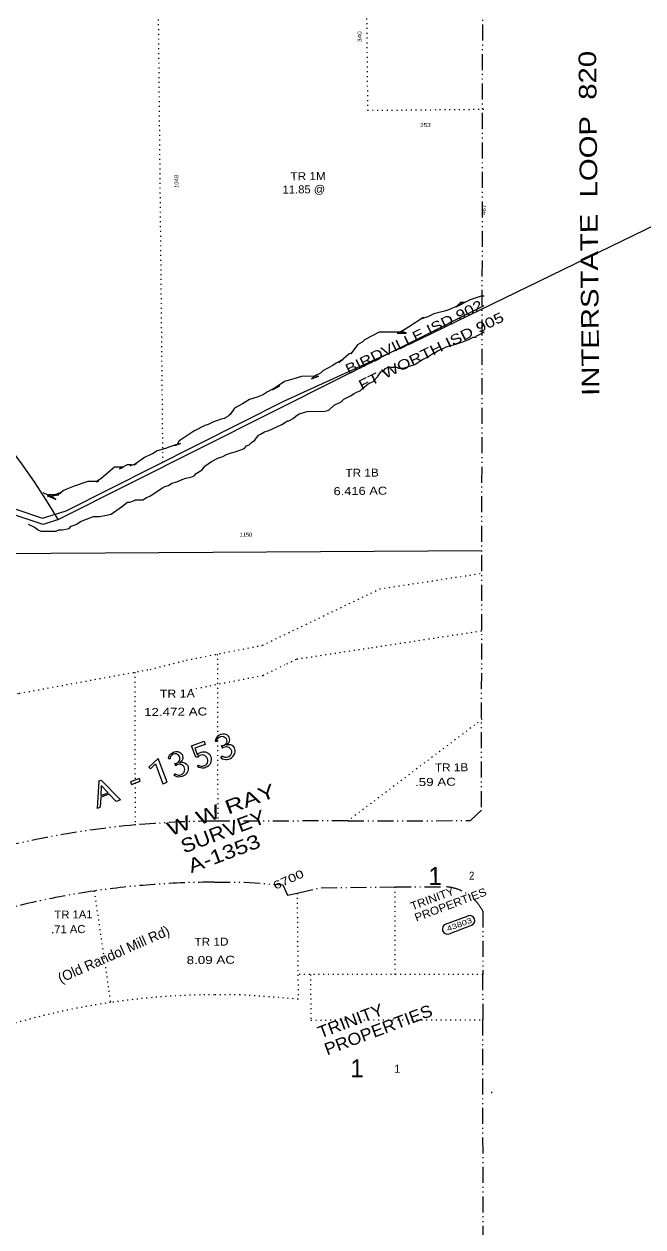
# Model space of a CAD drawing. Extents: x 2356373 to 2371954, y 6966197 to 6989612.
# Drawn here: x 2363330 to 2364566, y 6968599 to 6971002 of the extents above; entities that cross this region are included whole.
import ezdxf

# ---------------------------------------------------------------- set-up
doc = ezdxf.new("R2010")
doc.units = 0
doc.header["$LTSCALE"] = 6.4
doc.linetypes.add('DASH_DOUBLE_DOT', pattern=[9.2, 5, -1.2, 0.3, -1.2, 0.3, -1.2])
doc.linetypes.add('DOTTED', pattern=[1.5, 0.3, -1.2])
for name, color, linetype in [('10', 7, 'Continuous'), ('11', 7, 'Continuous'), ('18', 7, 'Continuous'), ('20', 7, 'Continuous'), ('21', 7, 'Continuous'), ('22', 7, 'Continuous'), ('24', 7, 'Continuous'), ('25', 7, 'Continuous')]:
    doc.layers.add(name, color=color, linetype=linetype)
for name, color, linetype, lineweight in [('12', 7, 'Continuous', 13), ('15', 7, 'Continuous', 13), ('16', 7, 'DOTTED', 13), ('17', 7, 'Continuous', 13), ('19', 7, 'Continuous', 13), ('23', 7, 'Continuous', 13), ('4', 7, 'Continuous', 13), ('5', 7, 'DOTTED', 13), ('8', 7, 'Continuous', 13)]:
    doc.layers.add(name, color=color, linetype=linetype, lineweight=lineweight)

msp = doc.modelspace()

# ---------------------------------------------------------------- linework, layer by layer
at = {"layer": '15', "linetype": 'DASH_DOUBLE_DOT'}
for p, q in [((2364243.948, 6969438.017), (2364247.165, 6971493.721)), ((2364243.66, 6969432.062), (2364222.253, 6969410.944)), ((2363977.113, 6969410.409), (2363710.454, 6969409.753)), ((2363977.113, 6969410.409), (2364222.253, 6969410.944)), ((2364071.25, 6969278.679), (2364166.419, 6969278.924)), ((2364246.32, 6969229.78), (2364246.5, 6969103.93)), ((2364247.455, 6969013.165), (2364246.5, 6969103.93)), ((2364251.572, 6966626.517), (2364246.452, 6969018.362))]:
    msp.add_line(p, q, dxfattribs=at)
at = {"layer": '15'}
msp.add_line((2364264.196, 6968869.35), (2364264.225, 6968866.351), dxfattribs=at)
msp.add_line((2364264.196, 6968869.35), (2364264.225, 6968866.351), dxfattribs=at)
at = {"layer": '15', "linetype": 'DASH_DOUBLE_DOT'}
for points in [[(2363710.112, 6969288.003), (2363769.752, 6969288.106), (2363847.171, 6969282.389), (2363856.423, 6969261.967), (2363875.643, 6969266.149)], [(2363875.643, 6969266.149), (2363923.391, 6969276.974), (2364071.249, 6969278.688)]]:
    msp.add_lwpolyline(points, dxfattribs=at)
for centre, radius, start, end in [((2363714.863, 6967616.669), 1793.09, 90.14089, 95.20879), ((2363714.863, 6967616.669), 1793.09, 95.20879, 105.95539), ((2363712.995, 6967614.916), 1673.09, 90.09871, 98.33989), ((2363712.995, 6967614.916), 1673.09, 98.33989, 106.91324), ((2364166.651, 6969188.925), 90, 27.33233, 90.1476)]:
    msp.add_arc(centre, radius, start, end, dxfattribs=at)
at = {"layer": '16'}
msp.add_lwpolyline([(2364248.654, 6970831.173), (2364017.008, 6970828.899), (2364013.67, 6971168.774)], dxfattribs=at)
at = {"layer": '17'}
for p, q in [((2363712.229, 6969569.95), (2363715.735, 6969569.184)), ((2364172.174, 6969203.816), (2364217.495, 6969220.657)), ((2364179.355, 6969185.092), (2364224.178, 6969201.928))]:
    msp.add_line(p, q, dxfattribs=at)
for points in [[(2363726.024, 6969539.643), (2363723.558, 6969536.219), (2363726.571, 6969534.649), (2363729.581, 6969533.629), (2363733.085, 6969533.114), (2363736.083, 6969533.243), (2363739.575, 6969533.978), (2363742.562, 6969535.258), (2363745.044, 6969537.031), (2363747.521, 6969539.305), (2363749.494, 6969541.922), (2363750.966, 6969544.886), (2363751.936, 6969547.796), (2363751.906, 6969550.844), (2363751.378, 6969553.838), (2363750.35, 6969556.578), (2363748.326, 6969559.007), (2363745.81, 6969560.833), (2363743.298, 6969562.106), (2363740.293, 6969562.628), (2363737.296, 6969562.397), (2363734.307, 6969561.468), (2363736.292, 6969562.887), (2363738.273, 6969564.706), (2363739.752, 6969566.97), (2363740.724, 6969569.48), (2363741.199, 6969572.134), (2363740.675, 6969574.827), (2363740.148, 6969577.371), (2363738.626, 6969579.656), (2363736.609, 6969581.484), (2363734.095, 6969582.91), (2363730.588, 6969583.777), (2363727.088, 6969583.842), (2363723.595, 6969583.108), (2363720.112, 6969581.674), (2363717.134, 6969579.495), (2363714.661, 6969576.72), (2363713.194, 6969573.508), (2363712.229, 6969569.95)], [(2363715.735, 6969569.184), (2363715.71, 6969571.733), (2363716.686, 6969574.142), (2363718.165, 6969576.256), (2363720.149, 6969577.925), (2363722.637, 6969578.999), (2363725.133, 6969579.423), (2363727.634, 6969579.147), (2363730.142, 6969578.273), (2363732.158, 6969576.694), (2363733.677, 6969574.709), (2363734.7, 6969572.319), (2363735.225, 6969569.726), (2363734.752, 6969567.121), (2363733.774, 6969564.763), (2363732.295, 6969562.75), (2363729.809, 6969561.224), (2363727.319, 6969560.351), (2363724.824, 6969560.076), (2363726.365, 6969555.792), (2363724.824, 6969560.076), (2363726.365, 6969555.792), (2363728.847, 6969557.416), (2363731.337, 6969558.389), (2363734.334, 6969558.718), (2363736.837, 6969558.345), (2363739.347, 6969557.319), (2363741.361, 6969555.639), (2363743.383, 6969553.51), (2363744.407, 6969550.971), (2363744.932, 6969548.275), (2363744.46, 6969545.572), (2363743.487, 6969542.813), (2363742.01, 6969540.5), (2363739.528, 6969538.626), (2363737.042, 6969537.402), (2363734.048, 6969536.873), (2363731.047, 6969537.093), (2363728.538, 6969538.068), (2363726.024, 6969539.643)], [(2363712.229, 6969569.95), (2363715.735, 6969569.184), (2363712.229, 6969569.95)], [(2363622.105, 6969534.073), (2363618.599, 6969534.84), (2363622.105, 6969534.073)], [(2363633.234, 6969520.686), (2363631.193, 6969524.966), (2363633.234, 6969520.686)], [(2363726.024, 6969539.643), (2363723.558, 6969536.219), (2363726.024, 6969539.643)], [(2363629.927, 6969501.108), (2363632.393, 6969504.532), (2363629.927, 6969501.108)], [(2363678.709, 6969521.983), (2363676.737, 6969519.165), (2363678.709, 6969521.983)]]:
    msp.add_lwpolyline(points, dxfattribs=at)
for points in [[(2363648.381, 6969505.388), (2363649.856, 6969507.703), (2363650.83, 6969510.461), (2363651.304, 6969513.167), (2363650.777, 6969515.861), (2363649.752, 6969518.4), (2363647.732, 6969520.529), (2363645.715, 6969522.208), (2363643.206, 6969523.234), (2363640.703, 6969523.608), (2363637.707, 6969523.279), (2363635.217, 6969522.306), (2363633.234, 6969520.686), (2363631.193, 6969524.966), (2363634.19, 6969525.195), (2363636.179, 6969526.114), (2363638.664, 6969527.638), (2363640.144, 6969529.651), (2363641.121, 6969532.01), (2363641.594, 6969534.615), (2363641.071, 6969537.209), (2363640.046, 6969539.598), (2363638.527, 6969541.583), (2363636.512, 6969543.112), (2363634.005, 6969544.038), (2363631.503, 6969544.313), (2363629.008, 6969543.887), (2363626.519, 6969542.814), (2363624.535, 6969541.147), (2363623.056, 6969539.032), (2363622.079, 6969536.622), (2363622.105, 6969534.073), (2363618.599, 6969534.84), (2363619.564, 6969538.397), (2363621.032, 6969541.611), (2363623.504, 6969544.385), (2363626.482, 6969546.564), (2363629.967, 6969547.997), (2363633.459, 6969548.732), (2363636.957, 6969548.665), (2363640.467, 6969547.8), (2363642.979, 6969546.375), (2363644.997, 6969544.544), (2363646.518, 6969542.262), (2363647.044, 6969539.717), (2363647.57, 6969537.023), (2363647.096, 6969534.368), (2363646.121, 6969531.86), (2363644.643, 6969529.595), (2363642.661, 6969527.777), (2363640.677, 6969526.358), (2363643.667, 6969527.287), (2363646.662, 6969527.517), (2363649.668, 6969526.996), (2363652.179, 6969525.722), (2363654.697, 6969523.897), (2363656.72, 6969521.467), (2363657.747, 6969518.728), (2363658.275, 6969515.733), (2363658.306, 6969512.685), (2363657.336, 6969509.776), (2363655.864, 6969506.812), (2363653.891, 6969504.194), (2363651.414, 6969501.92), (2363648.931, 6969500.146), (2363645.945, 6969498.867), (2363642.454, 6969498.133), (2363639.454, 6969498.003), (2363635.95, 6969498.519), (2363632.942, 6969499.539), (2363629.927, 6969501.108), (2363632.393, 6969504.532), (2363634.908, 6969502.958), (2363637.917, 6969501.988), (2363640.417, 6969501.762), (2363643.413, 6969502.291), (2363645.898, 6969503.516), (2363648.381, 6969505.388)], [(2363692.757, 6969516.721), (2363689.767, 6969515.843), (2363686.27, 6969515.66), (2363682.765, 6969516.124), (2363679.255, 6969517.339), (2363676.737, 6969519.165), (2363678.709, 6969521.983), (2363681.222, 6969520.658), (2363683.729, 6969519.832), (2363686.23, 6969519.607), (2363688.727, 6969520.031), (2363691.216, 6969520.956), (2363693.2, 6969522.424), (2363695.182, 6969524.343), (2363696.659, 6969526.608), (2363697.132, 6969529.262), (2363697.105, 6969532.011), (2363696.58, 6969534.655), (2363695.556, 6969537.094), (2363693.536, 6969539.173), (2363691.521, 6969540.805), (2363689.012, 6969541.828), (2363686.507, 6969542.255), (2363683.511, 6969541.974), (2363681.021, 6969541.05), (2363678.537, 6969539.576), (2363677.057, 6969537.562), (2363673.554, 6969537.877), (2363664.834, 6969560.586), (2363689.735, 6969569.879), (2363692.299, 6969563.205), (2363671.383, 6969555.452), (2363676.515, 6969541.806), (2363678.491, 6969544.173), (2363680.973, 6969546.049), (2363683.957, 6969547.427), (2363686.449, 6969548.252), (2363689.446, 6969548.481), (2363692.45, 6969548.061), (2363695.458, 6969547.09), (2363697.972, 6969545.566), (2363700.492, 6969543.49), (2363702.015, 6969541.057), (2363703.542, 6969538.322), (2363704.071, 6969535.378), (2363704.1, 6969532.33), (2363703.631, 6969529.326), (2363702.664, 6969526.017), (2363701.193, 6969523.003), (2363698.719, 6969520.38), (2363696.241, 6969518.256), (2363692.757, 6969516.721)], [(2363592.706, 6969524.487), (2363607.597, 6969484.443), (2363616.065, 6969487.527), (2363598.104, 6969534.938), (2363579.776, 6969517.912), (2363582.808, 6969514.543), (2363592.706, 6969524.487)], [(2363484.061, 6969491.528), (2363522.932, 6969452.671), (2363514.466, 6969449.438), (2363500.325, 6969464.095), (2363483.393, 6969457.681), (2363482.591, 6969437.577), (2363477.113, 6969435.475), (2363480.574, 6969490.246), (2363484.061, 6969491.528)], [(2363483.362, 6969460.78), (2363498.304, 6969466.326), (2363484.161, 6969481.332), (2363483.362, 6969460.78)], [(2363545.127, 6969482.98), (2363562.061, 6969489.445), (2363560.507, 6969494.778), (2363543.076, 6969488.31), (2363545.127, 6969482.98)]]:
    msp.add_lwpolyline(points, close=True, dxfattribs=at)
for centre, start, end in [((2364220.586, 6969211.295), 290.56276, 110.56276), ((2364175.764, 6969194.459), 110.56276, 290.56276)]:
    msp.add_arc(centre, 9.997, start, end, dxfattribs=at)
at = {"layer": '23'}
for points in [[(2363414.02, 6970029.786), (2363850.745, 6970249.519), (2364123.451, 6970373.865), (2364831.881, 6970717.933), (2365090.947, 6970907.728), (2365131.196, 6970983.103), (2365499.957, 6971099.096), (2365745.133, 6971176.384), (2365908.693, 6971318.452), (2366016.367, 6971450.575)], [(2361736.506, 6969313.397), (2361856.463, 6969314.575), (2361996.962, 6969361.742), (2362090.297, 6969426.942), (2362123.339, 6969523.541), (2362263.567, 6969598.299), (2362349.636, 6969690.819), (2362368.682, 6969787.381), (2362357.915, 6969865.754), (2362295.204, 6970041.491), (2362521.874, 6970374.229), (2362630.364, 6970423.382), (2362757.7, 6970385.543), (2363200.677, 6970070.678), (2363367.181, 6970014.731), (2363414.02, 6970029.786)]]:
    msp.add_lwpolyline(points, dxfattribs=at)
at = {"layer": '4'}
msp.add_line((2360061.937, 6969925.881), (2364244.75, 6969950.412), dxfattribs=at)
at = {"layer": '5', "linetype": 'Continuous'}
msp.add_line((2363398.338, 6970012.187), (2364249.534, 6970439.768), dxfattribs=at)
at = {"layer": '5'}
for p, q in [((2364024.04, 6969756.457), (2364244.937, 6969790.146)), ((2363716.296, 6969743.535), (2363717.114, 6969409.77)), ((2363875.065, 6969733.736), (2364019.936, 6969755.831)), ((2363807.146, 6969701.04), (2363851.398, 6969722.343)), ((2363855.32, 6969724.231), (2363875.065, 6969733.736)), ((2363551.38, 6969707.454), (2363552.076, 6969402.354)), ((2363664.342, 6969673.051), (2363807.146, 6969701.04)), ((2364245.315, 6969613.433), (2363977.113, 6969410.409)), ((2363470.321, 6969270.313), (2363502.945, 6969047.696)), ((2364071.5, 6969103.679), (2364071.25, 6969278.679)), ((2364246.5, 6969103.93), (2363877.283, 6969103.401))]:
    msp.add_line(p, q, dxfattribs=at)
for points in [[(2364013.67, 6971168.774), (2363596.821, 6971164.68), (2363607.111, 6970117.06)], [(2363221.955, 6969340.683), (2363083.697, 6969567.425), (2363044.821, 6969611.819), (2363108.677, 6969634.872), (2363174.686, 6969645.694), (2363320.71, 6969665.189), (2363582.098, 6969713.083), (2363654.728, 6969731.465), (2363806.637, 6969761.245), (2364040.422, 6969873.802), (2364244.679, 6969904.963)], [(2363875.643, 6969266.149), (2363877.775, 6969054.52), (2363761.642, 6969063.096), (2363710.492, 6969063.008)], [(2363902.24, 6969103.437), (2363903.195, 6969012.672), (2364247.455, 6969013.165)]]:
    msp.add_lwpolyline(points, dxfattribs=at)
at = {"layer": '5', "linetype": 'Continuous'}
msp.add_lwpolyline([(2363399.198, 6970012.146), (2363368.305, 6970002.145), (2363223.868, 6970050.513), (2362779.888, 6970365.867), (2362626.481, 6970411.347), (2362489.134, 6970348.715), (2362254.566, 6970005.802), (2362313.172, 6969840.621)], dxfattribs=at)
msp.add_arc((2361987.831, 6969171.803), 1641.882, 30.78676, 79.82976, dxfattribs=at)
at = {"layer": '5'}
for start, end in [(98.34001, 107.38687), (90.09871, 98.34001)]:
    msp.add_arc((2363712.986, 6967614.92), 1448.09, start, end, dxfattribs=at)
at = {"layer": '8'}
for points in [[(2364249.492, 6970458.481), (2364243.588, 6970458.423), (2364221.668, 6970450.909), (2364192.82, 6970436.13), (2364202.717, 6970446.325), (2364210.714, 6970446.403), (2364190.818, 6970436.41), (2364183.844, 6970434.042), (2364179.868, 6970431.705), (2364172.893, 6970429.236), (2364148.96, 6970423.102), (2364137.022, 6970417.186), (2364126.061, 6970413.479), (2364129.044, 6970415.209), (2364127.043, 6970415.189), (2364098.237, 6970396.311), (2364089.288, 6970391.425), (2364081.339, 6970386.349), (2364075.36, 6970384.29), (2364094.356, 6970384.476), (2364089.333, 6970386.825), (2364039.351, 6970386.335), (2364010.509, 6970370.956), (2364005.555, 6970366.308), (2363996.607, 6970361.522), (2363982.79, 6970343.091), (2363984.768, 6970345.311), (2363978.799, 6970342.351), (2363958.969, 6970325.561), (2363962.924, 6970329.999), (2363966.912, 6970331.239), (2363953.981, 6970324.413), (2363947.028, 6970319.846), (2363927.136, 6970309.453), (2363922.183, 6970304.805), (2363911.239, 6970299.401), (2363904.301, 6970293.233), (2363919.245, 6970298.478), (2363884.259, 6970298.135), (2363869.312, 6970293.09), (2363850.365, 6970288.205), (2363827.523, 6970272.783), (2363826.539, 6970271.076), (2363841.457, 6970279.019), (2363839.458, 6970279), (2363816.579, 6970267.278), (2363808.63, 6970262.302), (2363805.648, 6970260.573), (2363795.693, 6970256.377), (2363780.737, 6970252.329), (2363766.83, 6970243.295), (2363750.914, 6970234.94), (2363742.046, 6970221.958), (2363739.062, 6970220.33), (2363738.077, 6970218.721), (2363733.105, 6970216.072), (2363731.122, 6970214.353), (2363730.126, 6970214.043), (2363722.15, 6970211.865), (2363707.203, 6970206.82), (2363698.25, 6970202.233), (2363691.277, 6970199.866), (2363669.394, 6970188.454), (2363639.597, 6970168.566), (2363636.655, 6970162.838), (2363630.687, 6970159.58), (2363631.678, 6970160.39), (2363642.64, 6970164.197), (2363633.664, 6970161.809), (2363621.707, 6970157.793), (2363612.745, 6970154.206), (2363595.794, 6970149.641), (2363586.856, 6970143.554), (2363584.866, 6970142.734), (2363570.935, 6970136.1), (2363550.08, 6970121.8), (2363554.061, 6970123.637), (2363542.105, 6970119.521), (2363545.082, 6970121.75), (2363536.086, 6970121.662), (2363521.166, 6970113.817), (2363529.135, 6970116.794), (2363511.141, 6970116.618), (2363483.375, 6970093.55), (2363474.436, 6970087.765), (2363479.421, 6970089.114), (2363474.43, 6970088.164), (2363457.438, 6970087.998), (2363430.535, 6970078.837), (2363410.619, 6970070.642), (2363400.69, 6970063.847), (2363404.668, 6970065.986), (2363386.731, 6970060.011), (2363385.738, 6970059.301), (2363399.711, 6970061.738), (2363380.718, 6970061.55), (2363376.741, 6970059.213), (2363379.741, 6970059.141), (2363393.804, 6970052.282), (2363386.761, 6970056.912), (2363368.678, 6970065.931)], [(2363338.305, 6970002.95), (2363352.368, 6969996.09), (2363359.413, 6969991.361), (2363364.433, 6969989.111), (2363394.423, 6969989.305), (2363399.398, 6969991.753), (2363406.396, 6969991.822), (2363420.368, 6969994.258), (2363424.32, 6969998.997), (2363432.295, 6970001.374), (2363436.27, 6970003.811), (2363443.221, 6970008.579), (2363455.171, 6970013.295), (2363469.12, 6970018.132), (2363481.116, 6970018.249), (2363495.088, 6970020.685), (2363504.061, 6970023.173), (2363524.916, 6970037.374), (2363536.82, 6970046.889), (2363541.818, 6970046.937), (2363548.793, 6970049.306), (2363552.767, 6970051.744), (2363567.764, 6970051.791), (2363574.714, 6970056.559), (2363581.689, 6970059.027), (2363585.665, 6970061.366), (2363606.518, 6970075.665), (2363611.494, 6970078.014), (2363618.469, 6970080.381), (2363625.421, 6970085.149), (2363635.393, 6970087.646), (2363646.344, 6970092.352), (2363653.318, 6970094.82), (2363663.291, 6970097.217), (2363670.266, 6970099.686), (2363674.219, 6970104.323), (2363686.145, 6970111.539), (2363691.074, 6970118.585), (2363704.977, 6970128.119), (2363718.902, 6970135.254), (2363725.878, 6970137.621), (2363734.828, 6970142.408), (2363741.803, 6970144.875), (2363751.776, 6970147.274), (2363770.702, 6970154.459), (2363774.652, 6970159.195), (2363779.628, 6970161.643), (2363784.581, 6970166.291), (2363791.532, 6970171.058), (2363798.437, 6970180.522), (2363802.413, 6970182.962), (2363810.364, 6970187.638), (2363819.337, 6970190.126), (2363835.262, 6970197.281), (2363845.212, 6970202.076), (2363852.165, 6970206.845), (2363856.141, 6970209.183), (2363859.139, 6970209.213), (2363868.09, 6970213.999), (2363873.041, 6970218.746), (2363879.993, 6970223.512), (2363888.966, 6970225.9), (2363895.943, 6970228.268), (2363930.93, 6970228.611), (2363938.904, 6970230.988), (2363949.807, 6970240.495), (2363963.734, 6970247.63), (2363968.685, 6970252.376), (2363982.613, 6970259.512), (2363989.563, 6970264.278), (2363994.539, 6970266.727), (2364001.513, 6970269.094), (2364006.466, 6970273.842), (2364017.369, 6970283.347), (2364027.32, 6970288.044), (2364036.224, 6970297.528), (2364043.129, 6970306.993), (2364048.105, 6970309.442), (2364052.058, 6970314.079), (2364057.032, 6970316.528), (2364074.024, 6970316.695), (2364078.048, 6970314.335), (2364088.044, 6970314.433), (2364101.993, 6970319.268), (2364110.967, 6970321.656), (2364124.869, 6970331.19), (2364134.821, 6970335.987), (2364148.723, 6970345.42), (2364150.723, 6970345.441), (2364157.674, 6970350.208), (2364164.649, 6970352.575), (2364173.599, 6970357.362), (2364192.547, 6970362.246), (2364206.495, 6970367.082), (2364211.47, 6970369.43), (2364218.445, 6970371.898), (2364227.396, 6970376.585), (2364232.394, 6970376.635), (2364234.37, 6970379.053), (2364249.652, 6970386.884)]]:
    msp.add_lwpolyline(points, dxfattribs=at)

# ---------------------------------------------------------------- texts
at = {"layer": '10'}
for s, width, p in [('TR 1M', 1.1, (2363862.417, 6970689.817)), ('TR 1B', 1.1, (2363972.208, 6970097.454)), ('TR 1A', 1.15, (2363601.611, 6969656.358)), ('TR 1B', 1.1, (2364150.942, 6969508.966)), ('TR 1A1', 1.05, (2363391.03, 6969215.178)), ('TR 1D', 1.1, (2363670.681, 6969160.684))]:
    msp.add_text(s, height=15.99, rotation=0.563, dxfattribs=dict(at, width=width)).set_placement(p)
at = {"layer": '11'}
for s, width, p in [('11.85 @', 1.05, (2363846.682, 6970663.268)), ('6.416 AC', 1.2, (2363948.572, 6970060.93)), ('12.472 AC', 1.25, (2363569.978, 6969619.758)), ('.59 AC', 1.25, (2364111.236, 6969479.883)), ('.71 AC', 1.05, (2363384.321, 6969185.72)), ('8.09 AC', 1.25, (2363655.042, 6969124.24))]:
    msp.add_text(s, height=15.99, rotation=0.563, dxfattribs=dict(at, width=width)).set_placement(p)
at = {"layer": '12', "width": 0.9}
msp.add_text('2', height=15.99, rotation=0.563, dxfattribs=at).set_placement((2364219.045, 6969292.892))
at = {"layer": '12'}
msp.add_text('1', height=15.99, rotation=0.563, dxfattribs=at).set_placement((2364069.874, 6968907.329))
at = {"layer": '17', "width": 1.35}
msp.add_text('43803', height=10.5, rotation=20.563, dxfattribs=at).set_placement((2364176.815, 6969189.327))
at = {"layer": '18', "width": 1.1}
for s, height, p in [('TRINITY', 15.99, (2364105.677, 6969231.594)), ('PROPERTIES', 15.99, (2364113.897, 6969209.082)), ('TRINITY', 23.99, (2363922.243, 6968975.562)), ('PROPERTIES', 23.99, (2363935.569, 6968941.901))]:
    msp.add_text(s, height=height, rotation=20.563, dxfattribs=at).set_placement(p)
at = {"layer": '19', "width": 1.25}
msp.add_text('INTERSTATE  LOOP  820', height=34.99, rotation=90.563, dxfattribs=at).set_placement((2364479.48, 6970259.393))
at = {"layer": '19'}
msp.add_text('(Old Randol Mill Rd)', height=19.99, rotation=23.948, dxfattribs=at).set_placement((2363403.295, 6969086.133))
at = {"layer": '20'}
for s, width, p in [('W W RAY', 1.35, (2363622.354, 6969379.506)), ('SURVEY', 1.15, (2363649.684, 6969345.085)), ('A-1353', 1.25, (2363664.068, 6969305.736))]:
    msp.add_text(s, height=27.99, rotation=20.563, dxfattribs=dict(at, width=width)).set_placement(p)
at = {"layer": '21'}
for s, width, p in [('BIRDVILLE ISD 902', 1.25, (2363978.197, 6970301.958)), ('FT WORTH ISD 905', 1.3, (2364004.5, 6970270.324))]:
    msp.add_text(s, height=19.99, rotation=25.909, dxfattribs=dict(at, width=width)).set_placement(p)
at = {"layer": '22'}
for p in [(2364138.173, 6969282.1), (2363981.987, 6968898.169)]:
    msp.add_text('1', height=35.99, rotation=0.563, dxfattribs=at).set_placement(p)
at = {"layer": '24', "width": 1.35}
msp.add_text('6700', height=15.99, rotation=24.015, dxfattribs=at).set_placement((2363832.346, 6969272.898))
at = {"layer": '25'}
for s, rotation, width, p in [('340', 90.563, 1.2, (2364004.663, 6970966.14)), ('253', 0.563, 1.2, (2364121.304, 6970795.932)), ('1048', 90.563, 1.1, (2363638.626, 6970674.52)), ('467', 90.563, 1.2, (2364252.997, 6970619.972)), ('1150', 0.563, 0.95, (2363761.439, 6969977.714))]:
    msp.add_text(s, height=7.997, rotation=rotation, dxfattribs=dict(at, width=width)).set_placement(p)

doc.saveas('drawing.dxf')
